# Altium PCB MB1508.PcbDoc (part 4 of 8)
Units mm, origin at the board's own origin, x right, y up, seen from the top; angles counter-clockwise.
Board outline 129 x 77 mm, 4 copper layers (Top Layer, GND, POWER, Bottom Layer), stack 1.582 mm thick; 399 components, 297 nets, 1407 pads, 1316 vias.
Unrouted connection lines stored in the file: 535.
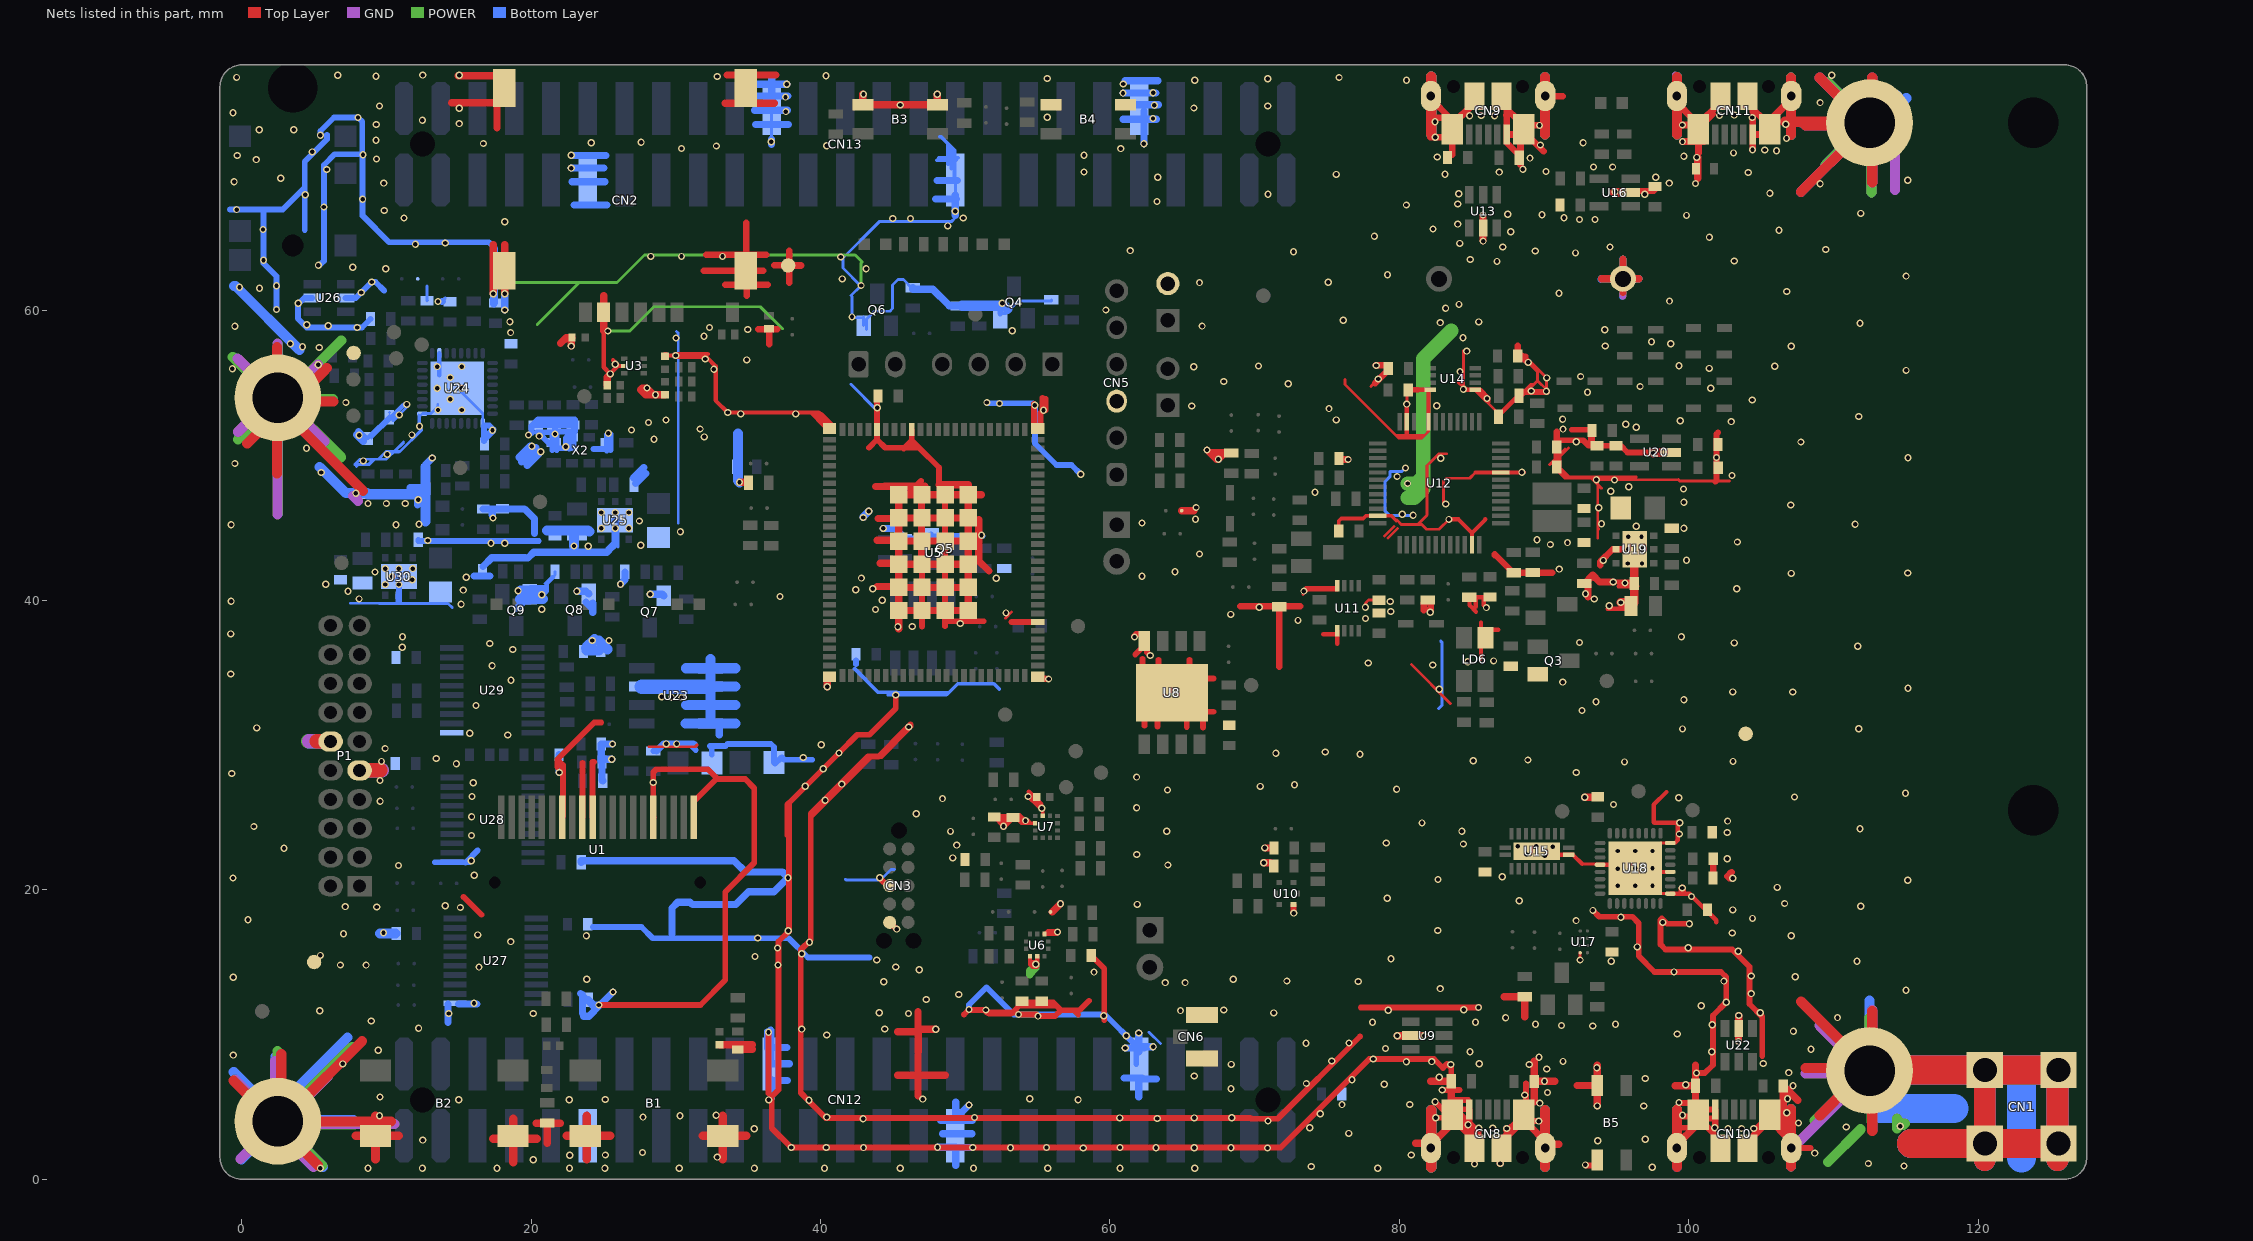
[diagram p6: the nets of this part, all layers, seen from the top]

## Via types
v1: diameter 0.5, hole 0.3, Top Layer to Bottom Layer, tented both sides, 1301 vias
v2: diameter 0.65, hole 0.4, Top Layer to Bottom Layer, tented both sides, 14 vias
v3: diameter 0.5/0.5/0.5/0.5 (per signal layer), hole 0.3, Top Layer to Bottom Layer, tented both sides, 1 vias

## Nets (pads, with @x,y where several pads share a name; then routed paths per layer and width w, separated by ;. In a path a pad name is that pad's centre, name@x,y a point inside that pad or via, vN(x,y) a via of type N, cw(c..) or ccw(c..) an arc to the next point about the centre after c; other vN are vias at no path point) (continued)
GND: B1.3 B1.4 B2.3 B2.4 B3.1 B3.3 B4.1 B4.3 B5.1 B5.3 BT1.2 C2.2 C3.1 C4.1 C5.1 C6.1 C7.1 C8.1 C9.1 C10.1 C11.2 C12.2 C13.1 C14.1 C15.1 C16.1 C17.2 C18.2 C19.1 C20.1 C21.2 C22.1 C23.1 C24.1 C25.1 C26.1 C27.2 C28.1 C29.2 C30.2 C31.1 C32.2 C33.1 C34.1 C35.2 C36.1 C37.1 C38.2 C39.2 C40.1 C41.1 C42.1 C43.1 C44.1 C45.2 C46.2 C47.2 C48.1 C49.1 C50.2 C51.2 C52.2 C54.1 C55.2 C56.1 C57.2 C58.2 C59.2 C60.2 C61.2 C62.2 C63.2 C64.2 C65.2 C66.1 C67.2 C68.2 C69.2 C70.2 C71.1 C72.1 C73.2 C74.1 C75.1 C77.1 C80.1 C82.1 C84.2 C86.2 C87.1 C88.1 C89.1 C90.1 CN1.1 CN1.2 CN1.3 CN1.4 CN2.2 CN2.3 CN2.4 CN2.5 CN2.C5 CN3.3 CN3.5 CN5.3 CN6.2 CN6.3 CN8.5 CN8.6 CN8.7 CN8.8 CN8.9 CN8.10 CN8.11 CN9.5 CN9.6 CN9.7 CN9.8 CN9.9 CN9.10 CN9.11 CN10.5 CN10.6 CN10.7 CN10.8 CN10.9 CN10.10 CN10.11 CN11.5 CN11.6 CN11.7 CN11.8 CN11.9 CN11.10 CN11.11 CN12.10 CN12.19 CN12.30 CN12.39 CN13.10 CN13.19 CN13.30 CN13.39 H1.1 H2.1 H3.1 H4.1 JP4.2 LD6.1 P1.5 P1.16 Q3.2 Q4.2 Q5.2 Q6.2 Q7.2 Q8.2 Q9.2 R2.1 R9.2 R11.1 R30.2 R36.1 R46.2 R48.2 R49.2 R51.1 R53.2 R55.1 R56.1 R58.1 R60.1 R61.1 R66.1 R67.1 R68.1 R71.1 R73.2 R77.1 R78.2 R79.1 R80.1 R84.2 R86.1 R87.1 R92.1 R94.1 R95.1 R103.2 R105.2 R106.2 R107.1 R111.1 R112.1 R116.1 R117.1 R123.2 SB13.2 SB24.2 SB52.1 TP1.1 TP2.1 TP12.1 TP25.1 U1.7 U1.9 U1.10 U1.16 U1.20 U3.2 U4.2 U5.6 U5.28 U5.42 U5.46 U5.51 U5.79 U5.102 U5.103 U5.104 U5.105 U5.106 U5.107 U5.108 U5.109 U5.110 U5.111 U5.112 U5.113 U5.114 U5.115 U5.116 U5.117 U5.118 U5.119 U5.120 U5.121 U5.122 U5.123 U5.124 U5.125 U5.126 U6.3 U6.8 U6.9 U7.6 U7.8 U8.4 U8.9 U9.2 U10.5 U11.4 U11.5 U12.8 U12.20 U12.23 U12.35 U12.47 U13.2 U14.4 U14.5 U15.10 U15.21 U16.2 U17.D1 U18.4 U18.17 U18.20 U18.24 U18.33 U19.2 U19.EP U20.2 U21.2 U22.2 U23.1 U23.2 U23.3 U23.4 U23.7 U24.1 U24.9 U24.18 U24.33 U25.2 U25.EP U26.2 U26.5 U27.11 U28.11 U29.11 U30.2 U30.EP X2.2 | length 2194.6
  Top Layer w0.2: 28.157,29.881 31.346,29.881 31.484,30.019 ; 39.211,52.983 39.279,52.983 U5.51@40.23,52.031 ; 39.401,24.998 43.543,29.14 ; 39.566,52.948 U5.51@40.281,52.233 ; 39.827,52.882 40.613,52.096 U5.51@40.613,51.869 ; 39.962,52.909 U5.51@40.796,52.075 ; 40.081,52.919 40.796,52.204 U5.51@40.796,52.075 ; U5.51@40.796,52.025 U5.51@40.796,52.075 ; B3.3@42.925,74.25 v1@42.925,74.933 ; 43.722,29.12 44.195,29.12 46.328,31.253 46.328,31.44 ; C7.1@43.913,54.045 C7.1@43.977,54.11 ; 52.775,38.762 53.207,39.193 ; v1@72.696,18.39 v1(72.698,18.387) ; 73.34,40.394 73.645,40.7 75.699,40.7 U11.4@75.699,41.001 ; 73.535,40.891 U11.4@75.589,40.891 ; U11.5@75.652,38.108 U11.5@75.699,38.155 ; 76.248,55.246 76.248,54.909 79.947,51.21 81.566,51.21 82.019,51.663 U12.20@82.019,52.338 ; v1(77.654,39.518) 77.654,39.792 77.876,40.014 C22.1@78.585,40.014 ; 78.035,54.789 v1(78.535,55.289) 78.61,55.289 78.681,55.289 C24.1@79.224,55.832 ; 78.971,44.438 79.628,45.094 ; 79.225,44.313 79.882,44.969 ; 79.761,51.406 80.519,51.406 81.741,51.406 ; 79.833,45.549 80.153,45.229 81.257,45.229 ; 79.839,51.35 80.519,51.35 81.459,51.35 ; v1(80.519,53.558) 80.519,54.431 C23.1@80.633,54.546 ; 80.832,35.559 83.533,32.858 ; 81.976,51.646 U12.20@81.976,52.287 ; U14.4@82.019,54.414 U14.4@82.151,54.546 ; v1(83.209,46.653) 83.124,46.653 83.057,46.721 83.057,48.231 83.264,48.438 84.865,48.438 85.264,48.838 ; 83.272,50.131 82.749,50.131 82.138,49.52 82.123,49.52 81.912,49.309 81.912,45.884 81.257,45.229 ; v1(83.426,45.591) 82.749,44.914 81.885,44.914 81.57,45.229 81.257,45.229 ; v1@84.428,57.25 84.428,54.771 v1(84.428,54.591) v1@84.473,54.546 ; U14.5@85.251,54.546 85.251,54.519 R55.1@86.851,52.919 ; R56.1@87.987,53.809 R56.1@88.331,54.153 ; R56.1@88.261,54.153 R56.1@88.331,54.153 ; R56.1@88.296,54.118 R55.1@86.851,52.673 86.851,52.855 88.451,54.456 R56.1@88.451,54.519 ; v1(88.47,48.856) 88.607,48.856 v1@88.589,48.838 ; v1(88.912,56.441) 89.557,55.795 89.557,55.175 ; v1@88.954,56.598 v1(90.18,55.372) 90.163,55.355 v1@90.163,54.569 ; 89.253,54.931 89.108,54.931 R56.1@88.331,54.153 ; U15.21@89.506,22.658 U15.21@89.756,22.408 ; 89.556,55.173 89.557,55.175 ; v1(90.163,54.454) v1@90.163,54.569 ; 90.369,49.373 90.884,49.889 91.101,50.106 ; 90.545,49.535 C30.2@90.617,49.463 ; C30.2@90.596,49.441 C30.2@90.617,49.463 ; C30.2@90.723,49.553 90.884,49.391 C30.2@90.999,49.277 ; C30.2@90.999,49.364 C30.2@90.999,49.277 ; C30.2@91.101,48.812 C30.2@91.101,48.979 ; C31.1@91.101,50.353 91.101,50.106 ; 91.424,48.446 91.634,48.446 ; 91.458,50.463 91.101,50.106 ; 91.685,50.531 91.101,49.947 ; 91.812,48.464 91.76,48.515 ; v1(92.491,15.148) 92.491,15.642 U17.D1@92.499,15.65 ; 92.633,21.779 93.822,21.779 U18.4@93.872,21.729 ; 93.131,50.677 C34.1@93.131,51.459 ; 93.303,48.4 93.709,47.995 ; v1(93.618,48.333) 99.273,48.333 99.278,48.338 99.365,48.25 101.886,48.25 102.806,48.25 ; 93.709,44.313 93.709,44.863 93.779,44.933 93.709,45.003 93.709,47.995 ; 93.958,47.745 93.709,47.995 ; 94.506,48.446 93.362,48.446 ; 96.374,48.515 93.292,48.515 ; U18.33@97.395,20.381 v1(97.497,20.279) 98.047,19.729 U18.17@98.722,19.729 ; U18.33@97.395,22.577 v1(97.497,22.679) 98.047,23.229 U18.24@98.722,23.229 ; R56.1@88.331,54.153 88.537,54.153 88.779,54.395 89.557,55.173 89.557,55.175 ; 89.557,55.175 v1@90.163,54.569 ; C30.2@90.617,49.463 90.884,49.73 91.101,49.947 ; C30.2@90.617,49.463 C30.2@90.999,49.081 ; C30.2@90.999,49.081 C30.2@90.999,49.277 ; C30.2@90.999,49.081 90.999,48.862 91.345,48.515 91.565,48.515 ; C30.2@90.999,49.081 C30.2@91.101,48.979 ; C30.2@90.999,49.277 C30.2@91.101,49.175 ; C30.2@91.101,48.979 C30.2@91.101,49.175 ; C30.2@91.101,48.979 91.565,48.515 ; C30.2@91.101,49.175 91.101,49.947 ; C30.2@91.101,49.175 91.76,48.515 ; 91.101,49.947 91.101,50.106 ; 91.565,48.515 91.634,48.446 ; 91.565,48.515 91.76,48.515 ; 91.634,48.446 93.362,48.446 ; 91.76,48.515 93.292,48.515 ; 93.292,48.515 93.362,48.446 ; 93.362,48.446 93.709,48.099 93.709,47.995
  Top Layer w0.254: C10.1@53.45,25.031 53.885,24.596 54.525,24.596 ; C10.1@53.685,25.084 v1@53.983,24.786 ; 53.774,25.184 v1@54.173,24.786 ; 53.811,24.786 v1@53.983,24.786 ; v1@54.119,24.65 v1@53.983,24.786 ; v1@54.209,24.75 v1@54.173,24.786 ; v1@54.781,14.846 v1(54.883,14.846) v1@54.98,14.943 ; U7.8@54.846,24.596 54.525,24.596 ; v1@55.352,25.562 55.352,25.116 U7.6@55.359,25.109 ; U6.3@55.48,16.939 55.699,17.157 56.38,17.157 v1@56.453,17.157 ; v1@56.328,17.132 v1(56.38,17.08) ; C19.1@75.815,44.793 75.815,45.477 75.988,45.65 77.51,45.65 77.697,45.838 U12.35@78.519,45.838 79.462,45.838 79.792,45.508 ; v1@53.983,24.786 v1@54.173,24.786 ; v1@54.173,24.786 54.336,24.786 54.525,24.596
  Top Layer w0.3: 25.015,58.602 25.015,56.109 v1(25.476,55.648) ; 25.663,55.87 v1@25.987,56.194 ; 25.663,56.594 26.025,56.232 v1@25.987,56.194 ; v1(25.821,56.308) 25.936,56.194 v1@25.987,56.194 ; U3.2@26.448,56.194 v1@25.987,56.194 ; C4.1@29.255,56.871 29.303,56.918 v1(29.991,56.918) ; 31.001,57.018 32.22,57.018 ; 31.799,56.918 v1(32.043,56.673) ; v1@32.149,56.779 32.752,56.177 32.752,53.818 v1(33.587,52.983) 39.211,52.983 ; 39.279,52.983 39.888,52.983 39.962,52.909 ; v1(54.345,26.442) 54.345,26.449 54.357,26.46 55.03,25.787 ; 54.396,26.771 55.254,25.913 v1@55.254,25.595 ; U6.8@54.48,15.414 54.48,15.005 ; v1@54.951,15.005 54.48,15.005 ; U6.9@54.98,15.414 54.98,14.943 54.98,14.707 54.963,14.689 54.622,14.689 54.48,14.831 54.48,15.005 ; 55.03,26.063 55.03,25.787 ; v1@55.281,25.536 55.03,25.787 ; U6.3@55.609,16.961 v1@56.38,16.961 ; SB13.2@55.893,18.466 SB13.2@56.012,18.466 ; v1@56.381,16.961 56.44,17.02 v1@56.479,17.058 ; 74.739,37.657 U11.5@75.642,37.657 ; 75.699,36.998 U11.5@75.699,37.901 ; 80.519,51.328 80.519,51.35 80.519,51.406 v1(80.519,53.558) ; C23.1@80.633,54.546 U14.4@82.151,54.546 ; U12.20@82.019,52.338 U14.4@82.019,54.414 ; v1(83.426,45.591) 84.09,45.591 85.019,44.662 ; 84.104,55.096 84.428,54.771 v1@84.654,54.546 ; v1@84.473,54.546 v1@84.654,54.546 ; U12.47@85.019,43.838 85.019,44.662 ; 85.264,48.838 v1@88.589,48.838 ; 85.287,39.558 R51.1@85.287,40.096 ; 85.299,39.213 84.845,39.667 R51.1@84.845,40.204 C28.1@85.827,40.204 ; U14.5@85.467,54.467 v1@86.033,53.9 ; 85.642,35.968 85.642,38.462 ; 85.827,39.671 C28.1@85.827,40.204 ; C28.1@85.827,40.208 C28.1@85.827,40.204 ; 85.948,45.591 85.019,44.662 ; 86.163,53.692 86.163,53.979 85.596,54.546 U14.5@85.251,54.546 v1@84.654,54.546 ; C28.1@86.267,40.23 86.242,40.204 C28.1@85.827,40.204 ; LD6.1@86.294,37.972 86.831,37.972 ; U15.21@89.756,22.408 U15.10@91.706,22.408 92.004,22.408 92.633,21.779 ; U18.4@93.872,21.729 U18.33@94.97,21.729 ; v1@94.39,39.417 C39.2@95.704,39.417 ; 95.045,41.289 96.233,41.289 C42.1@96.36,41.289 ; 95.148,40.961 96.233,40.961 C42.1@96.462,40.961 ; U18.33@97.623,21.229 U18.20@98.722,21.229 ; 98.459,26.759 97.57,25.87 97.57,24.675 97.616,24.629 97.84,24.629 97.845,24.634 v1@99.347,24.634 ; U18.17@98.722,19.729 100.058,19.729 101.899,17.887 101.899,17.751 ; U18.24@98.722,23.229 99.04,23.229 99.246,23.435 99.246,24.534 v1@99.347,24.634 ; v1(99.383,24.634) v1@99.347,24.634
  Top Layer w0.4: 15.34,19.504 16.566,18.278 ; 21.812,28.477 21.812,29.002 24.372,31.561 24.843,31.561 ; 21.93,28.894 22.2,28.625 22.2,27.768 22.211,27.757 22.211,25.06 U1.7@22.15,24.999 ; U1.9@23.55,24.999 23.55,28.778 ; U1.10@24.25,24.999 24.25,28.82 24.35,28.82 ; v1(24.685,12.033) 31.7,12.033 33.421,13.754 33.421,19.851 35.428,21.857 35.428,27.013 34.794,27.647 32.907,27.647 ; U1.16@28.45,24.999 28.443,25.005 v1(28.443,27.408) 28.443,28.115 28.652,28.324 32.23,28.324 32.907,27.647 ; U1.20@31.25,24.999 31.25,26.109 32.788,27.647 32.907,27.647 ; v1(36.402,10.145) 36.402,5.944 36.63,5.716 ; 37.708,23.769 37.708,25.881 37.817,25.99 ; U5.79@40.464,34.569 U5.79@40.613,34.719 ; 43.351,50.548 43.913,51.11 ; C7.1@43.913,54.045 U5.46@43.913,51.794 43.913,51.11 ; v1(44.088,20.822) 44.088,20.799 44.692,20.195 CN3.3@44.781,20.284 ; CN3.5@44.781,17.744 v1@45.259,17.266 ; v1(45.204,33.463) 45.204,32.527 44.289,31.613 44.289,31.61 43.384,30.705 42.532,30.705 v1(41.282,29.455) 37.817,25.99 ; U5.111@45.721,47.039 45.976,47.294 46.567,47.885 46.943,48.261 ; 45.751,50.485 45.814,50.548 ; v1@46.213,31.423 46.21,31.423 45.781,30.994 45.781,30.992 44.002,29.213 43.273,29.213 39.323,25.263 39.323,16.534 38.636,15.847 38.636,5.965 39.144,5.457 40.368,4.233 v1(60.674,4.233) v1(65.83,4.233) 69.707,4.233 69.76,4.18 71.599,4.18 77.281,9.862 ; 46.313,50.62 46.313,51.047 ; U5.42@46.313,51.794 46.313,51.047 ; 47.013,38.186 U5.117@47.013,39.294 U5.126@47.013,40.894 U5.125@47.013,42.494 U5.124@47.013,44.094 U5.123@47.013,45.694 U5.110@47.013,47.294 ; 48.185,47.993 48.185,49.175 46.812,50.548 ; 48.613,38.205 U5.118@48.613,39.294 U5.119@48.613,40.894 U5.120@48.613,42.494 U5.121@48.613,44.094 U5.122@48.613,45.694 U5.109@48.613,47.294 ; 48.832,38.558 51.287,38.558 ; 49.91,11.38 50.222,11.691 v1(51.428,11.691) 51.428,11.592 51.502,11.518 53.281,11.518 ; 51.644,11.43 53.193,11.43 53.281,11.518 ; 53.207,38.494 U5.6@55.013,38.494 ; v1(53.681,11.38) 54.919,11.38 v1(55.032,11.266) 56.213,11.266 56.622,11.675 ; v1(53.681,11.38) 53.544,11.518 53.281,11.518 ; C11.2@53.742,11.994 C11.2@53.757,11.994 ; v1@54.756,53.579 54.756,52.125 U5.28@55.013,51.869 55.213,52.069 55.213,52.936 v1@55.333,53.056 ; U5.102@55.013,34.719 v1(55.762,34.565) 55.772,34.554 U5.102@55.455,34.554 ; 55.333,53.997 v1@55.333,53.056 ; v1(55.412,53.135) v1@55.333,53.056 ; v1@55.567,53.135 55.567,53.926 ; 56.17,11.994 C11.2@53.757,11.994 ; 57.816,11.38 57.52,11.675 ; 58.552,12.336 57.892,11.675 57.52,11.675 ; C14.1@58.702,15.226 C14.1@58.702,15.451 59.604,14.549 59.604,10.988 ; v1@61.648,37.501 61.811,37.664 U8.4@62.358,37.664 ; 61.747,36.25 U8.4@62.134,36.637 ; U8.9@62.26,35.42 62.26,35.967 ; 62.392,31.331 U8.9@62.392,31.878 ; 62.557,36.417 v1(62.782,36.193) ; 63.28,31.289 U8.9@63.28,31.835 ; U8.9@63.348,35.345 63.348,35.892 ; 65.315,31.246 U8.9@65.315,31.793 ; U8.9@65.503,35.34 65.503,35.886 ; 66.424,31.216 U8.9@66.424,31.763 ; U8.9@66.603,34.588 67.15,34.588 ; U8.9@66.619,32.303 67.165,32.303 ; v1@72.696,18.39 U10.5@72.696,18.934 ; 77.333,11.859 v1(85.465,11.859) v1@85.516,11.91 ; C23.1@80.758,54.554 81.297,54.554 ; U9.2@80.773,9.915 U9.2@80.784,9.925 ; v1(82.472,5.351) CN8.6@83.039,4.784 ; v1(82.522,4.244) CN8.6@83.325,4.244 ; v1(82.962,6.166) 83.58,6.166 84.149,6.166 ; R46.2@83.58,6.76 83.58,7.703 83.304,7.98 83.012,7.688 82.403,8.297 78.197,8.297 v1(78.192,8.303) 77.918,8.303 71.8,2.184 v1(60.699,2.184) v1(55.619,2.184) v1(50.514,2.184) v1(40.405,2.184) v1(37.971,2.184) 36.63,3.525 36.63,5.716 ; CN8.6@83.61,4.857 CN8.6@83.667,4.8 ; CN8.6@83.755,5.473 CN8.5@84.762,5.473 ; CN8.6@83.796,4.838 CN8.5@84.803,4.838 ; CN8.5@84.83,4.153 CN8.5@84.83,5.16 ; C29.2@88.185,56.871 88.482,56.871 88.724,56.871 ; 88.586,54.395 88.779,54.395 v1@90.203,54.395 ; CN8.9@88.635,4.011 v1(89.641,4.011) ; CN8.9@88.756,5.138 88.756,6.633 ; 90.949,51.058 92.709,51.058 93.09,50.677 93.131,50.677 C44.1@94.985,50.677 95.315,50.677 95.776,50.217 v1@97.576,50.217 ; 91.92,51.788 C34.1@93.277,51.788 ; v1@92.906,0.954 B5.3@93.709,0.954 ; C43.1@93.32,50.94 C34.1@93.32,51.479 ; v1(93.375,18.572) 93.815,18.132 96.104,18.132 96.547,17.69 96.547,15.413 97.638,14.322 v1(98.977,14.322) 102.228,14.322 102.583,13.967 v1(102.583,12.231) 101.669,11.317 101.669,7.896 101.111,7.337 v1(100.53,7.337) ; U16.2@96.145,68.295 97.582,68.295 C26.1@97.865,68.577 ; 99.113,4.323 99.175,4.323 99.915,4.323 ; 99.219,3.552 CN10.6@100.021,3.552 ; v1@99.383,5.254 CN10.6@100.186,5.254 ; v1(100.044,17.651) 98.487,17.651 98.134,18.004 98.043,17.912 98.043,16.226 98.389,15.88 102.998,15.88 104.201,14.677 104.201,12.101 105.083,11.219 105.083,8.521 ; CN10.6@100.667,4.45 101.027,4.81 CN10.5@101.83,4.81 ; CN10.6@100.867,4.194 CN10.5@101.669,4.194 ; 101.83,48.194 101.886,48.25 101.913,48.277 101.913,51.487 102.026,51.6 ; CN10.11@107.601,2.15 108.403,2.15 ; 36.63,5.716 37.099,6.184 37.099,16.42 37.817,17.138 37.817,25.99 ; 43.913,51.11 44.475,50.548 45.814,50.548 ; 45.814,50.548 46.812,50.548 ; 45.814,50.548 46.313,51.047 ; 46.313,51.047 46.812,50.548 ; 53.281,11.518 C11.2@53.757,11.994 ; C11.2@53.757,11.994 53.978,12.215 56.082,12.215 56.622,11.675 ; 56.622,11.675 57.52,11.675
  Top Layer w0.45: 31.924,62.77 CN2.2@34.84,62.77 CN2.2@34.878,62.77 ; 32.117,63.894 CN2.2@34.878,63.894 ; 33.427,61.795 CN2.2@34.891,61.795 ; CN2.2@34.878,61.971 CN2.2@34.878,62.77 ; 34.878,66.097 CN2.2@34.878,63.894 ; 34.891,61.06 CN2.2@34.891,61.795 ; CN2.2@34.891,62.122 CN2.2@34.891,61.795 ; 35.684,58.744 R9.2@36.443,58.744 ; 36.05,62.77 CN2.2@34.878,62.77 ; 36.244,63.894 CN2.2@34.878,63.894 ; 36.343,61.795 CN2.2@34.891,61.795 ; 36.443,57.704 R9.2@36.443,58.744 ; R9.2@36.443,58.766 R9.2@36.443,58.744 ; 36.813,63.139 TP12.1@37.765,63.139 TP12.1@37.828,63.139 ; 37.017,58.744 R9.2@36.443,58.744 ; 37.828,61.939 37.828,63.137 TP12.1@37.828,63.139 ; TP12.1@37.828,63.138 38.652,63.138 ; 37.828,64.172 TP12.1@37.828,63.139 ; R30.2@67.934,50.179 R30.2@68.393,50.179 R30.2@68.369,50.203 ; 69.017,39.598 73.143,39.598 ; 71.695,35.396 R36.1@71.695,39.523 ; 78.319,54.999 78.61,55.289 C24.1@79.32,55.999 ; v1@78.364,56.232 v1(78.406,56.232) C24.1@79.114,56.232 ; 81.702,39.329 R49.2@81.702,39.809 ; R49.2@81.846,40.03 82.185,39.69 ; R49.2@82.109,39.794 82.185,39.718 82.185,39.69 ; 82.126,72.004 CN9.9@83.329,72.004 ; v1(82.128,39.183) 82.128,39.272 v1@82.185,39.329 ; CN9.11@82.422,74.404 CN9.9@83.272,73.554 ; 82.572,73.335 CN9.9@83.774,73.335 ; 83.665,70.803 CN9.9@83.665,72.005 ; CN8.6@84.103,3.778 CN8.7@84.83,3.051 ; CN9.9@84.295,73.448 CN9.8@85.265,74.419 ; v1@84.83,3.631 84.83,3.84 CN8.5@84.83,4.81 ; 86.587,43.113 86.587,43.184 87.873,41.898 R60.1@87.894,41.898 90.565,41.898 ; CN9.7@87.307,74.072 CN9.7@87.43,73.949 ; 87.385,73.529 87.43,73.485 ; CN9.7@87.43,74.85 CN9.7@87.43,73.949 ; CN9.6@88.157,73.222 CN9.7@87.43,73.949 ; C29.2@88.185,56.828 88.185,57.578 ; R48.2@88.28,70.59 88.28,70.762 87.43,71.612 CN9.5@87.43,72.19 ; CN9.6@88.632,72.19 CN9.5@87.43,72.19 ; CN9.6@88.728,72.818 v1@89.93,72.818 ; CN9.6@89.122,71.872 89.972,71.022 ; CN9.10@90.08,74.85 91.282,74.85 ; 90.104,73.14 CN9.10@90.104,74.342 ; C30.2@90.884,49.201 90.884,49.391 90.884,49.73 90.884,49.889 C31.1@90.884,50.59 90.884,51.633 ; 93.895,42.413 93.895,42.674 94.75,43.529 U19.2@94.973,43.529 U19.EP@96.273,43.529 ; CN10.6@101.103,3.778 CN10.7@101.83,3.051 ; C47.2@101.682,20.804 101.683,20.806 C48.1@101.683,22.138 ; v1@101.83,3.631 CN10.5@101.83,4.81 ; 102.954,21.223 102.659,20.928 102.796,20.791 v1(103.039,20.791) ; CN11.7@104.307,74.072 CN11.7@104.43,73.949 ; v1(104.405,71.14) 104.43,71.165 CN11.5@104.43,72.19 ; CN11.7@104.43,74.85 CN11.7@104.43,73.949 ; CN11.6@105.157,73.222 CN11.7@104.43,73.949 ; CN11.6@105.592,72.55 105.232,72.19 CN11.5@104.43,72.19 ; CN10.9@105.83,4.006 CN10.9@105.83,5.11 ; CN2.2@34.878,62.77 CN2.2@34.878,63.894 ; v1@82.185,39.329 82.109,39.405 82.185,39.481 ; v1@82.185,39.329 82.185,39.481 ; 82.185,39.481 82.185,39.69 ; CN9.5@87.43,72.19 87.43,73.485 ; 87.43,73.485 CN9.7@87.43,73.949 ; CN11.5@104.43,72.19 CN11.7@104.43,73.949
  Top Layer w0.5: 14.499,74.381 CN2.4@17.648,74.381 ; v1@14.968,76.252 CN2.4@17.987,76.252 ; v1(17.392,61.178) 17.392,64.566 ; 17.648,72.661 CN2.4@17.648,74.381 ; CN2.4@17.648,76.049 CN2.4@17.648,74.381 ; CN2.4@17.887,74.381 CN2.4@17.648,74.381 ; v1(18.18,61.185) 18.18,64.573 ; 20.339,3.868 R2.1@21.122,3.868 ; 21.122,2.474 R2.1@21.122,3.868 ; R2.1@21.122,3.884 R2.1@21.122,3.868 ; 22.034,57.757 22.427,58.151 C2.2@22.831,58.151 22.776,58.095 v1(22.776,57.568) ; 22.04,3.868 R2.1@21.122,3.868 ; 25.015,58.602 CN2.C5@25.015,59.895 25.015,61.049 ; C3.1@25.268,54.862 25.268,55.44 v1(25.476,55.648) ; v1(28.595,54.212) C5.1@29.237,54.212 ; C5.1@29.255,54.194 v1@28.488,54.194 ; C4.1@29.255,56.918 C4.1@29.303,56.918 ; v1(29.991,56.918) 31.799,56.918 ; C6.1@33.021,9.29 35.298,9.29 ; 33.424,74.346 36.812,74.346 ; 33.533,76.296 36.921,76.296 ; U4.2@34.278,8.97 35.293,8.97 ; v1(34.408,48.155) 34.997,48.155 R11.1@35.022,48.13 ; v1(40.464,34.029) U5.79@40.464,34.569 ; B3.3@42.913,74.262 v1@42.913,74.97 ; B3.3@42.925,74.25 B3.1@48.075,74.25 48.063,74.262 v1(48.063,74.97) ; 43.813,47.866 45.413,47.866 U5.111@45.413,47.294 ; 43.896,40.958 U5.115@45.413,40.958 ; 43.896,44.158 U5.113@45.413,44.158 ; 43.981,45.655 U5.112@45.413,45.655 ; 44.123,42.558 U5.114@45.413,42.558 ; 44.438,47.885 46.567,47.885 U5.110@47.209,47.885 ; 45.319,7.18 46.729,7.18 ; 45.319,10.18 46.729,10.18 46.729,11.59 ; v1@45.413,38.043 U5.116@45.413,39.294 ; U5.115@45.496,40.958 U5.115@45.413,40.958 ; U5.114@45.496,42.558 U5.114@45.413,42.558 ; U5.113@45.496,44.158 U5.113@45.413,44.158 ; U5.112@45.496,45.655 U5.112@45.413,45.655 ; 46.729,5.77 46.729,7.18 ; 46.729,8.59 46.729,7.18 ; 46.747,8.789 46.747,10.199 46.906,10.357 v1(47.968,10.357) ; U5.125@47.013,42.494 U5.120@48.613,42.494 U5.105@50.213,42.494 ; 48.185,47.993 50.213,47.993 U5.108@50.213,47.294 ; 48.632,7.18 46.729,7.18 ; U5.103@50.213,39.294 U5.118@48.613,39.294 U5.117@47.013,39.294 U5.116@45.413,39.294 ; U5.103@50.213,39.866 U5.104@50.213,40.894 ; 50.944,45.583 50.944,42.722 51.646,42.02 ; 51.106,47.294 U5.108@50.213,47.294 ; C9.1@52.008,25.031 52.039,25 C10.1@53.313,25 ; C9.1@52.225,24.977 v1@52.598,24.604 ; v1(52.641,24.382) 52.641,24.909 ; v1@52.736,24.528 C10.1@53.108,24.9 ; SB13.2@56.012,18.466 v1(56.584,19.038) ; SB24.2@64.961,46.195 65.789,46.195 ; v1(66.711,50.39) 67.36,49.741 v1(67.495,49.741) R30.2@67.934,50.179 ; 66.986,50.204 R30.2@68.393,50.204 ; v1(70.633,21.858) 71.102,21.858 C16.1@71.329,21.631 ; v1@70.749,22.885 C17.2@71.217,22.885 ; C18.2@75.906,49.86 76.029,49.736 v1(76.458,49.736) ; v1(79.856,9.915) U9.2@80.773,9.915 ; U9.2@80.784,9.925 80.794,9.915 v1(81.71,9.915) ; 81.131,2.483 CN8.10@82.044,2.483 ; 82.17,6.76 R46.2@83.58,6.76 83.58,6.166 CN8.6@83.58,5.35 ; CN8.10@82.171,2.785 82.171,3.698 ; 82.197,1.088 CN8.10@82.197,2.001 ; CN8.10@82.209,2.404 CN8.6@83.554,3.749 ; CN8.6@83.511,5.124 83.796,4.838 84.446,4.189 ; CN9.9@83.905,73.118 CN9.8@84.951,74.165 ; CN8.6@84.019,4.035 CN8.7@84.954,3.1 ; CN8.6@84.237,4.09 84.954,3.374 ; 84.476,4.194 84.83,3.84 85.411,3.259 85.411,2.718 CN8.7@85.192,2.5 ; CN8.7@85.199,1.265 CN8.7@85.199,2.178 ; CN9.8@85.289,74.903 CN9.8@85.295,74.909 ; v1(85.788,64.824) U13.2@85.788,65.724 v1(85.788,66.624) ; v1(86.973,1.088) CN8.8@86.973,2.001 ; CN8.8@87.114,2.751 87.42,3.057 CN8.8@87.42,3.068 ; 87.257,12.61 R53.2@88.667,12.61 88.667,11.2 ; CN8.8@87.309,2.835 87.697,3.224 CN8.9@88.355,3.882 ; CN8.8@87.417,3.065 CN8.8@87.42,3.068 ; v1@87.417,3.402 v1@87.496,3.307 ; v1(87.42,3.502) v1@87.496,3.307 ; v1@87.631,3.386 88.644,4.399 CN8.9@88.677,4.432 ; CN8.9@88.134,3.782 CN8.8@87.42,3.068 ; CN8.9@88.21,4.021 v1@87.496,3.307 ; R48.2@88.369,70.132 CN9.6@88.369,71.55 ; C29.2@88.482,56.871 v1(88.912,56.441) ; CN8.9@88.995,3.704 CN8.11@90.041,2.658 ; CN8.9@89.33,5.35 C25.1@89.33,6.76 ; 89.33,8.17 C25.1@89.33,6.76 ; 90.02,1.051 CN8.11@90.02,1.964 ; CN8.11@90.045,2.871 90.045,3.784 ; CN8.11@90.121,2.407 91.034,2.407 ; 90.74,6.76 v1(90.035,6.76) C25.1@89.33,6.76 ; 92.27,6.475 B5.1@93.68,6.475 ; R66.1@92.794,41.163 93.367,41.736 93.834,41.268 v1(94.785,41.268) ; v1(92.81,26.397) C33.1@93.652,26.397 ; 93.034,40.245 R66.1@93.034,41.055 ; v1(93.68,5.065) B5.1@93.68,6.475 ; v1@93.68,7.885 B5.1@93.68,6.475 ; C33.1@93.698,26.47 93.646,26.418 C33.1@93.709,26.418 ; 93.974,62.219 BT1.2@95.45,62.219 ; 95.45,61.284 BT1.2@95.45,62.219 ; 95.45,63.592 BT1.2@95.45,62.219 ; 96.541,62.219 BT1.2@95.45,62.219 ; 99.052,6.462 R67.1@100.462,6.462 ; CN10.10@99.209,2.404 CN10.6@100.554,3.749 ; CN11.11@99.219,74.342 CN11.9@100.265,73.296 ; 99.549,19.849 v1(99.549,20.119) ; v1(99.561,72.844) CN11.9@100.859,72.844 ; v1(99.568,71.7) CN11.9@100.675,71.7 ; CN10.6@100.462,5.052 R67.1@100.462,6.462 ; 100.462,7.872 R67.1@100.462,6.462 ; CN11.9@100.583,72.568 CN11.9@100.859,72.844 ; 100.62,69.162 v1@100.62,70.642 ; 100.675,70.92 CN11.9@100.675,71.7 ; CN11.9@100.675,72.4 CN11.9@100.675,71.7 ; CN11.9@100.905,73.118 CN11.8@101.951,74.165 ; CN11.9@101.041,72.844 CN11.9@100.859,72.844 ; CN11.9@101.047,71.7 CN11.9@100.675,71.7 ; 101.629,73.614 CN11.9@100.859,72.844 ; v1(103.435,9.509) 103.435,10.395 U22.2@103.455,10.415 v1(103.455,11.312) ; CN10.8@104.309,2.835 104.732,3.259 CN10.9@105.355,3.882 ; v1@104.631,3.386 105.644,4.399 CN10.9@105.677,4.432 ; CN11.6@105.706,73.251 CN11.10@107.051,74.596 ; CN10.9@105.995,3.704 106.53,3.169 ; CN10.11@107.041,2.658 106.53,3.169 ; 107.527,5.452 C49.1@106.53,6.449 106.53,3.957 106.53,3.169 ; v1@28.488,54.194 27.918,54.194 27.555,54.557 27.672,54.674 v1(28.007,54.674) v1@28.488,54.194 ; U5.116@45.413,39.294 U5.115@45.413,40.894 ; U5.115@45.413,40.894 U5.126@47.013,40.894 U5.119@48.613,40.894 U5.104@50.213,40.894 ; U5.115@45.413,40.894 U5.115@45.413,40.958 ; U5.115@45.413,40.958 U5.114@45.413,42.494 ; U5.114@45.413,42.494 46.972,42.494 U5.124@46.972,44.094 ; U5.114@45.413,42.494 U5.114@45.413,42.558 ; U5.114@45.413,42.558 U5.113@45.413,44.094 ; U5.113@45.413,44.094 U5.124@46.972,44.094 ; U5.113@45.413,44.094 U5.113@45.413,44.158 ; U5.113@45.413,44.158 U5.112@45.413,45.655 ; U5.112@45.413,45.655 U5.112@45.413,45.694 ; U5.112@45.413,45.694 U5.111@45.413,47.294 ; U5.112@45.413,45.694 U5.123@46.972,45.694 ; U5.111@45.413,47.294 45.976,47.294 U5.110@46.972,47.294 ; U5.124@46.972,44.094 U5.123@46.972,45.694 ; U5.124@46.972,44.094 U5.124@47.013,44.094 U5.121@48.613,44.094 U5.106@50.213,44.094 ; U5.123@46.972,45.694 U5.110@46.972,47.294 ; U5.123@46.972,45.694 U5.123@47.013,45.694 U5.122@48.613,45.694 U5.107@50.213,45.694 ; U5.110@46.972,47.294 U5.110@47.013,47.294 U5.109@48.613,47.294 U5.108@50.213,47.294 ; U5.104@50.213,40.894 U5.105@50.213,42.494 ; U5.105@50.213,42.494 U5.106@50.213,44.094 ; U5.106@50.213,44.094 U5.107@50.213,45.694 ; U5.107@50.213,45.694 U5.108@50.213,47.294 ; CN8.8@87.42,3.068 v1@87.496,3.307
  Top Layer w0.6: 7.874,3 B2.3@9.25,3 ; 9.25,1.39 B2.3@9.25,3 ; 9.25,4.376 9.25,3.976 B2.3@9.25,3 ; 10.86,3 B2.3@9.25,3 ; 17.397,2.801 B2.4@18.773,2.801 ; 18.773,1.192 B2.4@18.773,2.801 ; 18.773,4.178 B2.4@18.773,2.801 ; 20.383,2.801 B2.4@18.773,2.801 ; 22.468,3 B1.3@23.75,3 B1.3@23.844,3 ; 23.844,1.39 B1.3@23.844,3 ; 23.844,4.376 B1.3@23.844,3 ; 25.454,3 B1.3@23.844,3 ; 31.874,3 B1.4@33.25,3 ; 33.25,1.39 B1.4@33.25,3 ; 33.25,4.376 B1.4@33.25,3 ; 34.86,3 B1.4@33.25,3 ; 46.729,10.18 46.747,10.199 ; v1@94.83,68.176 U16.2@95.987,68.176 ; v1(95.3,39.854) 95.773,39.854 C39.2@96.014,39.613 96.233,39.832 96.233,40.961 C42.1@96.233,41.162 96.233,41.289 96.233,43.489 U19.EP@96.273,43.529 ; v1(97.541,50.182) 97.576,50.217 U20.2@98.803,50.217
  Top Layer w0.7: -0.575,6.819 5.279,0.965 ; 0.382,50.838 H1.1@1.616,52.072 ; 2.454,48.774 H1.1@2.454,52.559 ; 2.454,57.506 H1.1@2.454,52.629 ; H1.1@2.5,52.559 H1.1@2.454,52.559 ; H1.1@2.501,53.747 H1.1@3.571,53.747 ; H2.1@2.739,5.7 2.739,8.64 ; H2.1@3.595,4.823 8.324,9.551 ; H2.1@3.642,3.976 9.25,3.976 10.329,3.976 ; H1.1@3.664,52.287 8.392,47.558 ; 5.877,56.053 5.699,55.875 H1.1@3.571,53.747 ; 6.341,53.747 H1.1@3.571,53.747 ; 82.204,0.804 82.204,4.766 ; 82.204,72.234 82.204,76.196 ; 90.075,0.829 90.075,4.791 ; 90.075,72.209 90.075,76.171 ; 99.175,0.854 99.175,4.323 99.175,4.817 ; 99.175,72.183 99.175,76.146 ; 106.523,3.957 106.53,3.957 ; v1@106.649,73.068 107.075,73.068 ; 107.075,0.88 107.075,4.842 ; 107.075,72.158 107.075,73.068 ; 107.075,76.12 107.075,73.068 ; 107.744,12.29 H3.1@111.709,8.324 ; 107.744,68.21 H4.1@111.709,72.176 ; 108.069,7.693 H3.1@111.144,7.693 ; 108.069,72.807 H4.1@111.144,72.807 ; 109.05,4.388 H3.1@111.129,6.467 ; 109.05,76.112 H4.1@111.129,74.033 ; 112.681,3.332 112.681,11.612 ; 112.681,68.888 H4.1@112.681,73.068 ; 112.681,76.112 H4.1@112.681,73.068 ; H4.1@113.336,73.068 H4.1@112.681,73.068 ; H1.1@2.454,52.559 2.383,52.559 H1.1@2.454,52.629 ; H1.1@2.454,52.559 H1.1@2.454,52.629 ; H1.1@2.454,52.629 H1.1@3.571,53.747 ; 107.075,73.068 H4.1@112.681,73.068
  Top Layer w1: 5.182,30.246 P1.16@6.15,30.246 ; P1.5@8.15,28.246 9.58,28.246
  Top Layer w1.5: CN1.4@120.46,1.3 CN1.4@120.46,2.46 CN1.3@120.46,7.54 ; CN1.1@125.483,1.317 125.483,2.46 CN1.2@125.483,6.397
  Top Layer w2: 115.38,2.46 CN1.4@120.46,2.46 125.483,2.46 CN1.1@125.54,2.46 ; H3.1@115.38,7.54 CN1.3@120.46,7.54 CN1.2@125.54,7.54
  GND w0.45: 82.175,0.806 82.175,3.928 ; 82.185,73.072 82.185,76.194 ; 90.075,0.806 90.075,3.928 ; 90.085,73.072 90.085,76.194 ; 99.058,73.199 99.058,76.321 ; 99.175,0.806 99.175,3.928 ; 107.075,0.806 107.075,3.928 ; 107.085,73.072 107.085,76.194
  GND w0.5: 93.974,62.219 BT1.2@95.45,62.219 ; 95.45,61.025 BT1.2@95.45,62.219 ; 95.45,63.592 BT1.2@95.45,62.219 ; 96.541,62.219 BT1.2@95.45,62.219
  GND w0.7: -0.468,6.877 H2.1@2.319,4.09 ; -0.276,56.702 H1.1@2.476,53.95 ; -0.245,51.646 H1.1@1.7,53.591 ; -0.09,1.398 H2.1@1.989,3.477 ; 2.319,8.168 H2.1@2.319,4.09 ; H1.1@2.443,53.443 H1.1@2.476,53.476 ; 2.476,45.95 H1.1@2.476,52.451 ; 2.476,57.73 H1.1@2.476,53.95 ; H1.1@2.569,53.857 H1.1@2.476,53.95 ; H2.1@3.497,2.912 H2.1@2.319,4.09 ; H1.1@3.634,53.069 5.713,50.99 ; H2.1@3.856,3.807 10.543,3.807 ; H2.1@3.871,5.033 5.95,7.112 ; 4.972,0.832 2.319,3.485 H2.1@2.319,4.09 ; v1(5.287,56.287) H1.1@2.476,53.476 ; 7.709,47.219 8.051,46.876 ; CN10.11@107.744,2.71 H3.1@111.709,6.676 ; 107.744,68.21 H4.1@111.709,72.176 ; 107.75,73.024 H4.1@112.681,73.024 ; 108.069,7.307 H3.1@111.144,7.307 ; 108.069,72.807 H4.1@111.144,72.807 ; 109.05,10.612 H3.1@111.129,8.533 ; 109.05,76.112 H4.1@111.129,74.033 ; 112.681,3.388 112.681,11.668 ; 112.681,68.888 H4.1@112.681,71.453 ; 112.681,76.129 H4.1@112.681,73.024 ; H4.1@113.358,73.024 H4.1@112.681,73.024 ; H4.1@113.405,72.177 H4.1@112.681,71.453 ; 114.261,68.36 H4.1@114.261,71.3 ; H1.1@2.476,52.451 2.236,52.692 H1.1@2.476,52.932 ; H1.1@2.476,52.451 H1.1@2.476,52.932 ; H1.1@2.476,52.932 H1.1@2.476,53.476 ; H1.1@2.476,53.476 H1.1@2.476,53.95 ; H4.1@112.681,71.453 H4.1@112.681,73.024
  GND w1: 4.654,30.246 P1.16@6.15,30.246 ; P1.5@8.15,28.246 9.682,28.246
  GND w1.5: CN1.4@120.46,1.3 CN1.4@120.46,2.46 CN1.3@120.46,7.54 ; CN1.1@125.483,1.317 125.483,2.46 CN1.2@125.483,6.397
  GND w2: 115.38,2.46 CN1.4@120.46,2.46 125.483,2.46 CN1.1@125.54,2.46 ; H3.1@115.38,7.54 CN1.3@120.46,7.54 CN1.2@125.54,7.54
  POWER w0.2: 17.36,61.97 23.325,61.97 ; 20.425,59.07 23.325,61.97 ; v1(25.307,58.607) 26.823,58.607 28.505,60.289 35.842,60.289 37.364,58.766 ; v1(42.807,61.756) 42.807,63.3 42.883,63.376 42.398,63.862 27.835,63.862 25.943,61.97 23.325,61.97 ; 54.488,13.987 55.022,14.52 v1@55.022,14.877
  POWER w0.45: 82.175,0.806 82.175,3.928 ; 82.18,73.234 82.18,76.28 ; 89.948,0.806 89.948,3.928 ; 90.08,73.234 90.08,76.28 ; 99.175,0.806 99.175,3.928 ; 99.18,73.234 99.18,76.28 ; 107.075,0.806 107.075,3.928 ; 107.085,72.998 107.085,76.12
  POWER w0.5: 54.463,14.11 54.463,14.426 v1(54.883,14.846) ; 93.974,62.219 BT1.2@95.45,62.219 ; 95.45,61.025 BT1.2@95.45,62.219 ; 95.45,63.592 BT1.2@95.45,62.219 ; 96.541,62.219 BT1.2@95.45,62.219
  POWER w0.7: -0.618,56.824 H1.1@2.416,53.791 ; -0.497,6.843 H2.1@2.479,3.867 ; -0.262,51.113 H1.1@1.869,53.245 ; H2.1@0.853,5.67 H2.1@2.479,4.045 ; H2.1@1.1,3.791 H2.1@2.479,3.791 ; H1.1@1.738,53.375 1.807,53.307 H1.1@1.869,53.245 ; H1.1@2.152,53.229 H1.1@2.5,53.577 ; H1.1@2.321,53.92 H1.1@2.5,53.92 ; H1.1@2.454,52.559 H1.1@2.5,52.559 ; H2.1@2.479,2.158 H2.1@2.479,3.791 ; 2.479,8.845 H2.1@2.479,4.045 ; 2.5,46.013 H1.1@2.5,52.559 ; 2.5,57.696 H1.1@2.5,54 H1.1@2.5,53.92 ; H2.1@2.911,4.416 7.639,9.145 ; H1.1@2.964,53.799 6.875,49.887 ; H1.1@3.294,52.913 H1.1@2.565,53.642 ; H1.1@3.65,55.025 H1.1@2.544,53.92 ; H2.1@4.232,2.114 H2.1@2.555,3.791 ; v1@5.582,0.942 H2.1@2.733,3.791 ; 6.3,53.92 H1.1@2.843,53.92 ; 6.88,57.957 H1.1@2.843,53.92 ; 7.788,3.791 H2.1@2.733,3.791 ; 82.204,0.804 82.204,4.766 ; 82.204,72.234 82.204,76.196 ; 90.075,0.829 90.075,4.791 ; 90.075,72.209 90.075,76.171 ; 99.175,3.928 99.175,4.817 ; 99.175,72.183 99.175,76.146 ; 107.075,3.928 107.075,4.842 ; 107.075,72.158 107.075,76.12 ; 108.128,7.586 H3.1@111.32,7.586 ; 108.558,72.914 H4.1@111.75,72.914 ; 108.688,4.055 H3.1@111.754,7.121 ; 109.466,70.092 H4.1@112.532,73.158 ; 109.62,1.189 111.877,3.446 ; 109.62,75.811 H4.1@111.877,73.554 ; 109.796,10.238 H3.1@112.053,7.981 ; H3.1@112.5,7.959 112.5,11.151 ; 112.627,4 H3.1@112.627,8.826 ; 112.627,68.174 H4.1@112.627,73 ; H4.1@112.762,74.762 H4.1@114.176,73.348 ; H3.1@114.264,7.672 H3.1@114.557,7.379 ; 114.391,3.511 v1@114.391,3.587 ; 114.391,4.172 114.391,3.841 ; H1.1@1.869,53.245 H1.1@2.5,52.614 ; H1.1@1.869,53.245 H1.1@2.416,53.791 ; H1.1@2.416,53.791 H1.1@2.5,53.707 ; H1.1@2.416,53.791 H1.1@2.5,53.875 ; H2.1@2.479,3.791 H2.1@2.555,3.791 ; H2.1@2.479,3.791 H2.1@2.479,3.867 ; H2.1@2.479,3.867 H2.1@2.479,4.045 ; H2.1@2.479,3.867 H2.1@2.555,3.791 ; H2.1@2.479,4.045 H2.1@2.733,3.791 ; H1.1@2.5,52.559 2.555,52.559 H1.1@2.5,52.614 ; H1.1@2.5,52.559 H1.1@2.5,52.614 ; H1.1@2.5,52.614 H1.1@2.5,53.577 ; H1.1@2.5,53.577 H1.1@2.5,53.707 ; H1.1@2.5,53.577 H1.1@2.565,53.642 ; H1.1@2.5,53.707 H1.1@2.565,53.642 ; H1.1@2.5,53.707 H1.1@2.5,53.875 ; H1.1@2.5,53.875 H1.1@2.544,53.92 ; H1.1@2.5,53.875 H1.1@2.5,53.92 ; H1.1@2.5,53.92 H1.1@2.544,53.92 ; H1.1@2.544,53.92 H1.1@2.843,53.92 ; H2.1@2.555,3.791 H2.1@2.733,3.791 ; H1.1@2.565,53.642 H1.1@2.843,53.92 ; H4.1@114.176,73.348 H4.1@114.417,73.59 ; H4.1@114.176,73.348 H4.1@114.417,73.107 ; H4.1@114.176,73.348 113.807,72.98 H4.1@114.417,72.98 ; v1@114.391,3.587 v1@114.645,3.841 ; v1@114.391,3.587 114.391,3.841 ; 114.391,3.841 v1@114.645,3.841 ; H4.1@114.417,72.98 H4.1@114.417,73.107 ; H4.1@114.417,72.98 H4.1@114.544,72.98 ; H4.1@114.417,73.107 H4.1@114.417,73.59 ; H4.1@114.417,73.107 H4.1@114.544,72.98 ; H4.1@114.417,73.59 114.417,73.641 H4.1@114.442,73.615 ; H4.1@114.417,73.59 H4.1@114.442,73.615 ; H4.1@114.442,73.615 115.077,72.98 H4.1@114.544,72.98 ; v1@114.645,3.841 v1@114.722,3.841 ; v1@114.645,3.841 114.684,3.879 v1@114.722,3.841 ; v1@114.722,3.841 114.823,3.74 114.925,3.841 v1@114.722,3.841
  POWER w1: 4.613,30.246 P1.16@6.15,30.246 ; P1.5@8.15,28.246 9.687,28.246 ; 80.57,47.088 81.04,47.088 81.662,47.709 81.662,48.555 ; v1(80.571,48.069) 81.176,48.069 81.662,48.555 ; 83.595,58.621 81.662,56.688 81.662,48.555
  POWER w1.5: CN1.4@120.46,1.3 CN1.4@120.46,2.46 CN1.3@120.46,7.54 ; CN1.1@125.483,1.317 125.483,2.46 CN1.2@125.483,6.397
  POWER w2: 115.38,2.46 CN1.4@120.46,2.46 125.483,2.46 CN1.1@125.54,2.46 ; H3.1@115.38,7.54 CN1.3@120.46,7.54 CN1.2@125.54,7.54
  Bottom Layer w0.2: 7.508,39.799 9.477,39.799 9.491,39.786 14.262,39.786 14.552,39.495 ; 7.934,49.239 8.082,49.387 ; C80.1@8.766,51.191 10.207,52.631 R112.1@10.207,52.657 R112.1@10.268,52.657 ; C80.1@8.778,51.339 R112.1@10.218,52.779 ; C80.1@8.962,51.217 R112.1@10.402,52.657 ; 9.171,49.724 8.834,49.387 8.73,49.387 ; 9.314,49.752 9.457,49.752 ; v1@10.118,50.157 10.198,50.238 10.28,50.238 ; R112.1@10.207,52.967 R112.1@10.207,52.992 ; R112.1@10.222,52.611 R112.1@10.268,52.657 ; R112.1@10.471,52.412 11.498,53.439 11.498,53.571 11.184,53.571 11.098,53.485 ; 10.538,50.297 10.519,50.278 ; 10.88,50.238 10.503,50.238 ; 11.101,53.49 R112.1@10.268,52.657 ; 11.195,50.93 10.543,50.278 ; v1@11.4,53.536 11.333,53.536 10.454,52.657 R112.1@10.402,52.657 ; v1@12.241,51.885 U24.9@12.241,52.805 ; C67.2@12.797,60.696 C67.2@12.797,60.758 ; 12.797,61.714 C67.2@12.797,60.758 ; C67.2@12.848,60.707 C67.2@12.797,60.758 ; U24.33@13.552,53.525 13.552,53.366 13.086,52.9 U24.9@12.488,52.9 12.288,52.7 v1(12.288,52.025) 12.288,51.951 12.448,51.791 10.935,50.278 10.543,50.278 ; v1(13.568,60.652) 13.841,60.652 C62.2@14.069,60.881 ; U24.33@14.913,54.65 16.663,52.9 U24.1@16.663,52.225 ; 20.488,40.816 21.15,40.816 21.15,41.175 ; 20.961,41.152 R107.1@21.46,41.651 ; 21.077,41.101 21.15,41.175 ; R107.1@21.576,41.601 21.15,41.175 ; R107.1@21.65,41.978 21.65,41.753 21.15,41.254 21.15,41.175 ; C56.1@22.759,52.115 C56.1@22.884,52.115 ; 25.25,43.603 U25.2@25.638,43.991 ; 26.003,43.696 U25.EP@26.003,44.699 ; 30.05,58.58 30.171,58.459 30.171,45.346 ; v1@36.62,71.888 36.62,72.88 36.62,73.868 CN13.30@36.62,73.995 ; 41.712,20.729 41.769,20.672 44.153,20.672 44.872,21.39 45.126,21.39 ; 42.101,54.929 v1@43.893,53.137 ; Q6.2@42.973,58.978 42.973,59.588 42.912,59.527 42.177,59.527 v1(42.177,59.585) 42.177,60.998 42.113,61.062 v1@42.782,61.731 ; Q6.2@43.179,58.718 43.179,59.429 43.728,59.978 44.799,59.978 44.982,60.161 44.982,61.795 45.348,62.161 45.732,62.161 R79.1@46.38,61.514 ; 44.648,33.463 48.72,33.463 48.961,33.704 ; CN13.19@49.32,69.045 49.32,69.011 49.32,67.729 v1(49.32,66.878) 49.32,66.444 49.041,66.165 44.055,66.165 41.555,63.664 41.555,62.959 v1@42.782,61.731 ; Q4.2@52.422,59.82 52.799,59.82 53.666,60.687 55.955,60.687 R71.1@55.955,60.762 ; 62.705,10.155 63.485,9.374 ; v1(80.426,49.149) 80.172,48.895 79.343,48.895 79.343,48.537 79.021,48.215 79.021,46.152 79.301,45.872 v1(80.952,45.872) ; 82.712,32.513 82.934,32.735 82.934,37.103 82.861,37.176 ; 8.082,49.387 8.73,49.387 ; 8.082,49.387 7.816,49.387 8.179,49.75 9.093,49.75 ; 8.73,49.387 9.093,49.75 ; 9.093,49.75 9.455,49.75 9.457,49.752 ; 9.457,49.752 9.984,50.278 10.519,50.278 ; 9.457,49.752 10.005,49.764 v1@10.28,50.039 ; R112.1@10.268,52.657 R112.1@10.402,52.657 ; v1@10.28,50.039 10.28,50.238 ; v1@10.28,50.039 10.41,50.169 ; 10.28,50.238 10.342,50.238 ; 10.342,50.238 10.41,50.169 ; 10.342,50.238 10.479,50.238 ; 10.41,50.169 10.479,50.238 ; 10.41,50.169 10.422,50.157 10.503,50.238 ; 10.479,50.238 10.503,50.238 ; 10.479,50.238 10.519,50.278 ; 10.503,50.238 10.543,50.278 ; 10.519,50.278 10.543,50.278 ; v1@42.782,61.731 42.807,61.707 v1(42.807,61.756) v1@42.782,61.731
  Bottom Layer w0.254: 42.344,35.281 43.969,33.656 45.252,33.656 v1@45.214,33.619 ; v1(45.204,33.463) 45.204,33.608 v1@45.214,33.619 ; 48.03,70.405 CN13.19@48.806,70.405 ; 48.177,70.583 CN13.19@48.806,70.583 ; 48.257,72.044 48.305,72.044 49.259,71.091 CN13.19@49.259,70.583 ; CN13.19@48.806,70.151 CN13.19@48.806,70.405 ; 48.806,71.5 CN13.19@48.806,70.583 ; CN13.19@49.041,69.847 CN13.19@49.041,70.405 ; 49.041,71.195 CN13.19@49.041,70.583 ; CN13.19@49.32,69.045 49.259,69.106 CN13.19@49.259,70.405 ; CN13.19@49.378,70.405 CN13.19@49.259,70.405 ; CN13.19@49.525,70.583 CN13.19@49.259,70.583 ; 52.362,33.861 51.983,34.241 49.477,34.241 48.855,33.619 v1@45.214,33.619 ; CN13.19@48.806,70.405 CN13.19@48.806,70.583 ; CN13.19@48.806,70.405 CN13.19@49.041,70.405 ; CN13.19@48.806,70.583 CN13.19@49.041,70.583 ; CN13.19@49.041,70.405 CN13.19@49.041,70.583 ; CN13.19@49.041,70.405 CN13.19@49.259,70.405 ; CN13.19@49.041,70.583 CN13.19@49.259,70.583 ; CN13.19@49.259,70.405 CN13.19@49.259,70.583
  Bottom Layer w0.3: U24.33@13.663,55.564 U24.18@13.663,57.075
  Bottom Layer w0.4: -0.807,67.002 v1(-0.35,67.002) 1.505,67.002 ; v1(2.406,60.093) v1(2.406,61.744) 2.406,62.392 1.505,63.293 v1(1.505,63.497) 1.505,67.002 ; 4.363,65.591 4.363,68.526 ; U26.5@4.885,60.893 4.33,60.893 3.961,60.525 v1(3.905,60.525) 3.885,60.505 3.885,59.465 4.502,58.848 v1(7.982,58.848) 8.319,58.848 R111.1@8.91,59.44 ; v1(5.303,63.156) 5.382,63.156 5.684,63.458 v1(5.684,67.18) 5.684,70.089 6.419,70.824 v1@8.233,70.824 ; v1(5.442,72.133) 5.442,72.437 6.373,73.369 v1(8.041,73.369) 8.329,73.081 8.329,70.92 v1@8.233,70.824 ; 5.903,72.177 5.903,71.855 4.363,70.316 4.363,68.526 ; U26.2@7.185,60.893 7.886,60.893 v1(8.266,61.273) v1(8.995,62.002) 9.245,62.002 9.858,61.388 ; U30.2@10.866,40.343 v1(10.866,41.093) U30.EP@10.866,41.643 ; R117.1@12.206,44.183 12.206,44.091 20.526,44.091 ; C65.2@12.701,48.979 C65.2@12.701,49.376 ; 13.343,21.907 U28.11@14.531,21.907 15.494,21.907 ; 15.478,21.891 15.494,21.907 ; v1@15.72,21.907 15.494,21.907 ; 16.318,22.731 15.494,21.907 ; C59.2@16.747,50.997 16.747,52.083 17.116,52.083 v1@17.394,51.805 ; C60.2@17.531,60.553 17.531,64.31 17.094,64.746 10.187,64.746 8.36,66.573 v1(8.36,67.713) 8.36,70.697 v1@8.233,70.824 ; v1@20.037,51.547 20.037,52.07 20.469,52.503 23.016,52.503 23.033,52.485 23.033,51.668 22.85,51.668 ; R86.1@20.314,52.103 21.584,52.109 C56.1@22.884,52.115 ; 20.413,51.61 v1@21.498,51.61 ; v1@20.509,51.572 R87.1@21.277,50.805 ; 21.466,50.371 v1@21.466,51.457 ; R87.1@21.555,50.911 21.648,51.005 v1(21.648,51.492) R84.2@21.648,52.09 ; v1@21.73,51.668 22.85,51.668 ; 21.77,50.39 v1@21.77,51.475 ; 21.951,50.512 22.635,50.512 ; v1(22.392,50.618) 22.392,51.21 X2.2@22.635,51.453 ; 22.635,50.476 22.635,50.512 ; X2.2@22.635,51.561 X2.2@22.635,51.453 ; 22.85,51.703 22.85,51.668 ; 22.933,50.481 22.933,50.512 ; 22.933,51.566 22.933,50.512 ; 23.036,50.512 22.933,50.512 ; 24.263,17.419 27.636,17.419 28.405,16.65 37.809,16.65 39.132,15.326 43.384,15.326 ; 24.309,50.457 25.225,50.457 ; C64.2@24.854,30.065 C64.2@24.856,30.067 ; 25.225,50.353 25.225,50.457 ; v1@25.225,51.438 25.225,50.457 ; 25.395,50.457 25.225,50.457 ; 25.49,50.388 v1@25.49,51.473 ; R92.1@28.442,29.594 R92.1@28.667,29.594 ; 31.008,30.023 31.383,29.648 ; C55.2@32.487,29.335 32.487,29.805 32.355,29.937 33.433,29.937 33.569,30.073 36.562,30.073 36.78,29.856 C52.2@36.78,28.784 36.861,28.703 37.318,29.16 37.496,28.982 39.436,28.982 ; CN12.30@36.308,9.025 v1@36.308,10.222 ; v1(36.402,10.145) 36.402,10.194 36.562,10.354 36.62,10.296 36.62,9.099 36.62,7.979 CN12.30@36.62,7.955 ; 42.463,35.586 C51.2@42.463,35.856 ; R80.1@45.82,44.277 47.264,44.277 Q5.2@47.489,44.502 47.535,44.456 47.628,44.549 47.771,44.405 48.776,44.405 48.823,44.452 51.191,44.452 51.141,44.502 v1(51.125,44.502) ; v1(50.267,11.727) 50.267,12.049 51.477,13.26 53.356,11.38 v1(53.681,11.38) 59.664,11.38 61.82,9.224 61.82,9.157 61.82,9.064 CN12.10@61.82,7.955 ; v1(51.5,53.676) 51.563,53.612 54.689,53.612 v1(54.816,53.485) 54.816,50.84 56.301,49.356 57.344,49.356 v1(57.989,48.711) ; Q4.2@52.422,59.82 v1@52.422,60.357 ; 1.505,67.002 2.839,67.002 4.363,68.526 ; 22.635,50.512 X2.2@22.635,51.453 ; 22.635,50.512 22.933,50.512 ; X2.2@22.635,51.453 22.85,51.668
  Bottom Layer w0.45: 10.866,39.922 U30.2@10.866,40.343
  Bottom Layer w0.5: H1.1@2.377,54.212 H1.1@2.377,56.78 ; 2.47,48.469 H1.1@2.47,51.037 ; v1@7.947,51.446 8.395,50.998 ; 8.076,51.667 C80.1@8.524,51.219 ; 11.638,47.78 12.291,47.78 ; 12.155,46.587 12.155,47.24 ; C65.2@12.701,49.376 v1(13.163,49.838) ; 13.841,60.652 13.86,60.652 ; 14.252,10.829 U27.11@14.252,12.099 ; U27.11@14.976,12.099 v1@16.246,12.099 ; 16.066,41.678 17.164,41.678 ; R116.1@16.675,42.342 17.278,42.945 19.62,42.945 19.637,42.928 19.789,42.928 20.189,43.328 25.231,43.328 25.619,43.716 25.638,43.716 25.809,43.887 U25.2@25.809,44.223 U25.EP@25.809,45.523 ; C73.2@16.695,46.311 17.318,46.311 ; C59.2@16.755,51.139 17.33,51.714 v1(17.33,51.746) ; v1@17.318,45.91 17.318,46.311 ; C60.2@17.421,60.495 v1@17.421,61.128 ; v1(18.18,60.067) v1(18.18,61.185) ; 19.033,39.45 19.655,40.072 Q9.2@20.275,40.692 ; 19.336,49.562 19.418,49.644 ; 19.734,49.338 20.556,50.159 20.383,50.332 20.106,50.332 ; v1@19.945,50.67 19.168,49.894 19.418,49.644 ; 20.016,50.332 20.106,50.332 ; 20.23,44.642 20.23,45.636 19.554,46.311 17.318,46.311 ; 20.322,50.548 20.106,50.332 ; C74.1@21.926,29.328 21.926,28.102 21.928,28.1 v1(21.94,28.1) ; v1(22.777,69.869) 25.048,69.869 ; 22.844,68.923 25.114,68.923 ; v1@22.873,70.736 25.171,70.736 ; 22.967,67.317 25.237,67.317 ; v1(23.167,40.629) 23.8,40.629 Q8.2@23.981,40.448 ; 23.411,12.823 23.55,12.684 ; R106.2@23.461,21.886 23.461,22.012 34.029,22.012 34.806,21.235 37.353,21.235 v1(37.759,20.829) 36.794,19.864 35.022,19.864 34.144,18.986 31.146,18.986 30.99,19.142 30.143,19.142 29.733,18.732 29.733,16.939 ; 23.55,11.47 23.55,12.684 ; 23.55,12.74 23.55,12.684 ; 23.63,11.266 23.997,11.266 v1@24.764,12.033 ; Q8.2@23.8,39.864 24.248,39.416 ; R105.2@23.947,12.409 24.323,12.033 v1(24.685,12.033) v1@24.764,12.033 ; 24.269,39.168 Q8.2@24.269,39.801 ; 24.309,11.925 23.55,12.684 ; C64.2@24.854,30.065 24.854,28.871 C63.2@24.905,28.82 ; C64.2@24.856,30.067 v1(25.63,30.067) ; R103.2@24.95,27.525 24.905,27.57 C63.2@24.905,28.82 ; v1(25.572,29.016) 25.143,29.016 25.122,29.037 C63.2@24.905,28.82 ; v1@25.663,12.931 v1@24.764,12.033 ; v1(26.181,41.105) 26.482,41.407 R94.1@26.482,41.964 ; R95.1@27.088,48.473 27.788,49.174 ; R95.1@27.222,48.064 27.922,48.764 ; v1(28.23,40.415) 29.068,40.415 Q7.2@29.162,40.321 ; R92.1@28.667,29.594 29.146,30.073 31.22,30.073 31.274,30.019 ; 33.008,30.701 U23.4@33.008,31.334 ; 35.39,75.667 35.399,75.657 36.621,75.657 CN13.30@36.63,75.667 ; 35.435,73.868 36.62,73.868 v1@37.705,73.868 ; 35.47,74.851 CN13.30@36.63,74.851 ; 35.5,72.88 36.62,72.88 37.771,72.88 ; CN12.30@36.4,9.099 36.62,9.099 37.67,9.099 ; CN12.30@36.442,6.821 CN12.30@36.621,6.821 ; CN12.30@36.568,7.979 36.62,7.979 37.838,7.979 ; v1@36.621,5.613 CN12.30@36.621,6.821 ; CN12.30@36.621,6.884 CN12.30@36.621,6.821 ; v1@36.62,71.506 v1@36.62,71.888 ; CN13.30@36.63,73.919 CN13.30@36.63,74.851 ; 36.63,76.19 CN13.30@36.63,75.667 ; v1(37.66,75.667) CN13.30@36.63,75.667 ; 37.712,6.821 CN12.30@36.621,6.821 ; v1@37.74,74.851 CN13.30@36.63,74.851 ; v1(42.954,45.722) 42.954,45.78 v1(43.337,46.163) ; v1(44.338,44.969) 45.148,44.969 45.364,44.753 45.82,44.297 R80.1@45.82,44.277 ; R79.1@46.38,61.482 46.398,61.499 47.764,61.499 ; R79.1@46.38,61.597 46.38,61.514 47.75,61.514 47.764,61.499 ; 47.965,67.729 CN13.19@49.31,67.729 ; 48.06,69.011 49.32,69.011 CN13.19@49.47,69.011 ; v1(48.081,2.206) 49.351,2.206 CN12.19@49.351,2.184 ; 48.304,4.078 CN12.19@49.343,4.078 ; 48.431,3.132 50.463,3.132 ; CN12.19@49.241,4.053 CN12.19@49.343,4.053 ; CN12.19@49.244,2.184 CN12.19@49.351,2.184 ; 49.31,66.606 CN13.19@49.31,67.729 ; CN13.19@49.31,68.016 CN13.19@49.31,67.729 ; 49.343,5.323 CN12.19@49.343,4.078 ; 49.351,0.936 CN12.19@49.351,2.184 ; CN12.19@49.368,4.229 v1(50.267,5.127) ; CN13.19@49.375,67.729 49.32,67.729 CN13.19@49.31,67.729 ; R78.2@49.475,60.34 R78.2@49.492,60.357 ; CN12.19@49.574,4.078 CN12.19@49.343,4.078 ; 50.511,4.053 CN12.19@49.343,4.053 ; v1(50.514,2.184) CN12.19@49.351,2.184 ; v1(60.9,75.05) v1@63.171,75.05 ; 60.927,73.248 CN13.10@62.347,73.248 ; 60.982,6.987 CN12.10@62.253,6.987 ; v1(61.057,9.064) 61.82,9.064 CN12.10@61.995,9.064 ; 61.058,75.9 63.329,75.9 ; 61.082,74.239 63.353,74.239 ; CN12.10@61.659,9.157 61.82,9.157 CN12.10@61.995,9.157 ; CN12.10@61.953,6.928 CN12.10@61.995,6.928 ; 61.995,5.695 CN12.10@61.995,6.928 ; CN12.10@61.995,6.966 CN12.10@61.995,6.928 ; CN12.10@61.995,8.78 CN12.10@61.995,9.064 ; v1(61.995,10.106) CN12.10@61.995,9.157 ; v1(62.347,71.545) CN13.10@62.347,73.248 ; CN13.10@62.347,73.816 CN13.10@62.347,73.248 ; CN12.10@62.383,9.064 CN12.10@61.995,9.064 ; v1(62.985,9.157) CN12.10@61.995,9.157 ; v1@63.198,73.248 CN13.10@62.347,73.248 ; 63.223,6.928 CN12.10@61.995,6.928 ; 93.941,62.185 BT1.2@95.418,62.185 ; 95.418,60.991 BT1.2@95.418,62.185 ; 95.418,63.559 BT1.2@95.418,62.185 ; 96.509,62.185 BT1.2@95.418,62.185 ; 19.418,49.644 20.106,50.332 ; CN13.30@36.63,74.851 CN13.30@36.63,75.667 ; 47.764,61.499 48.896,60.368 ; 48.896,60.368 49.503,60.368 R78.2@49.495,60.36 ; 48.896,60.368 48.904,60.36 R78.2@49.495,60.36 ; CN12.19@49.343,4.053 CN12.19@49.343,4.078 ; R78.2@49.492,60.357 49.497,60.357 R78.2@49.495,60.36 ; R78.2@49.492,60.357 R78.2@49.495,60.36 ; CN12.10@61.995,9.064 CN12.10@61.995,9.157
  Bottom Layer w0.7: -0.544,7.397 H2.1@2.352,4.502 ; -0.53,61.723 -0.426,61.723 3.99,57.307 ; -0.22,56.426 H1.1@2.454,53.753 ; -0.14,51.349 H1.1@2.226,53.715 ; -0.021,1.365 H2.1@2.345,3.731 ; H2.1@0.904,5.578 H2.1@2.352,4.13 ; H2.1@1.05,4.07 H2.1@2.352,4.07 ; H2.1@2.352,1.777 H2.1@2.352,4.07 ; 2.352,8.464 H2.1@2.352,4.502 ; 2.454,50.407 H1.1@2.454,53.753 ; 2.454,57.095 H1.1@2.454,53.753 ; 2.5,46.013 H1.1@2.5,52.7 ; H2.1@2.581,5.061 7.309,9.789 ; H2.1@4.185,2.669 H2.1@2.784,4.07 ; 5.146,51.061 H1.1@2.454,53.753 ; 5.391,49.219 7.204,47.405 v1(7.896,47.405) 8.658,47.405 C82.1@8.734,47.33 C66.1@12.515,47.33 ; v1@5.633,0.85 H2.1@2.412,4.07 ; 7.737,4.07 H2.1@2.784,4.07 ; v1@9.56,16.981 C87.1@10.611,16.981 ; 12.7,45.435 C65.2@12.7,49.217 ; 19.231,40.072 19.655,40.072 Q9.2@19.929,40.072 ; v1@19.259,40.666 Q9.2@19.957,40.666 ; Q9.2@19.956,40.085 20.81,40.085 ; Q9.2@19.986,40.716 20.01,40.692 20.275,40.692 20.881,40.692 ; 21.102,44.837 23.923,44.837 24.016,44.744 ; v1(22.964,43.751) C70.2@22.964,44.449 ; C69.2@23.786,36.713 v1@24.39,37.317 ; C69.2@23.826,36.525 C61.2@24.68,36.525 ; 24.68,37.224 25.283,36.62 ; 30.675,31.491 U23.4@32.379,31.491 ; 30.7,32.766 U23.3@32.404,32.766 ; 30.7,35.306 U23.1@32.404,35.306 ; 32.404,35.94 U23.1@32.404,35.306 ; 34.108,31.496 U23.4@32.404,31.496 U23.3@32.404,32.766 ; 34.108,32.766 U23.3@32.404,32.766 ; 34.108,34.036 U23.2@32.404,34.036 ; 34.108,35.306 U23.1@32.404,35.306 ; 34.289,51.51 34.289,48.274 v1(34.408,48.155) ; R78.2@49.787,60.357 52.422,60.357 52.713,60.357 52.927,60.143 ; 82.204,0.804 82.204,4.766 ; 82.204,72.234 82.204,76.196 ; 90.075,0.829 90.075,4.791 ; 90.075,72.209 90.075,76.171 ; 99.175,0.854 99.175,4.817 ; 99.175,72.183 99.175,76.146 ; 107.075,0.88 107.075,4.842 ; 107.075,72.158 107.075,76.12 ; 108.431,7.586 H3.1@111.623,7.586 ; 108.558,72.914 H4.1@111.75,72.914 ; 109.339,10.408 H3.1@112.405,7.342 ; 109.466,70.092 H4.1@112.405,73.031 ; 109.493,4.689 H3.1@111.75,6.946 ; 109.62,75.811 H4.1@111.877,73.554 ; H4.1@110.327,73.031 H4.1@112.405,73.031 ; H3.1@112.5,7.5 112.5,12.326 ; H4.1@112.532,73.158 H4.1@112.405,73.031 ; 112.627,68.174 H4.1@112.627,73 ; H4.1@112.812,74.991 H4.1@114.07,73.733 ; H3.1@114.061,7.214 H3.1@114.751,6.524 ; H4.1@114.417,74.892 H4.1@114.417,74.08 ; 115.031,74.693 H4.1@114.417,74.08 ; H2.1@2.352,4.07 H2.1@2.412,4.07 ; H2.1@2.352,4.07 H2.1@2.352,4.13 ; H2.1@2.352,4.13 H2.1@2.412,4.07 ; H2.1@2.352,4.13 H2.1@2.352,4.502 ; H2.1@2.352,4.502 H2.1@2.784,4.07 ; H2.1@2.412,4.07 H2.1@2.784,4.07 ; U23.3@32.404,32.766 U23.2@32.404,34.036 ; U23.2@32.404,34.036 U23.1@32.404,35.306 ; H4.1@112.405,73.031 H4.1@113.368,73.031 ; H4.1@113.368,73.031 H4.1@114.417,73.031 ; H4.1@113.368,73.031 H4.1@113.981,73.644 ; H4.1@113.981,73.644 H4.1@114.07,73.733 ; H4.1@113.981,73.644 H4.1@114.417,73.209 ; H4.1@114.07,73.733 H4.1@114.417,74.08 ; H4.1@114.07,73.733 H4.1@114.417,73.387 ; H4.1@114.417,73.031 H4.1@114.417,73.209 ; H4.1@114.417,73.031 H4.1@114.595,73.031 ; H4.1@114.417,73.209 H4.1@114.417,73.387 ; H4.1@114.417,73.209 H4.1@114.595,73.031 ; H4.1@114.417,73.387 H4.1@114.417,74.08 ; H4.1@114.417,73.387 114.772,73.031 H4.1@114.595,73.031
  Bottom Layer w1: 4.679,30.246 P1.16@6.15,30.246 ; P1.5@8.15,28.246 9.428,28.246 ; U23.7@27.654,34.036 U23.2@32.404,34.036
